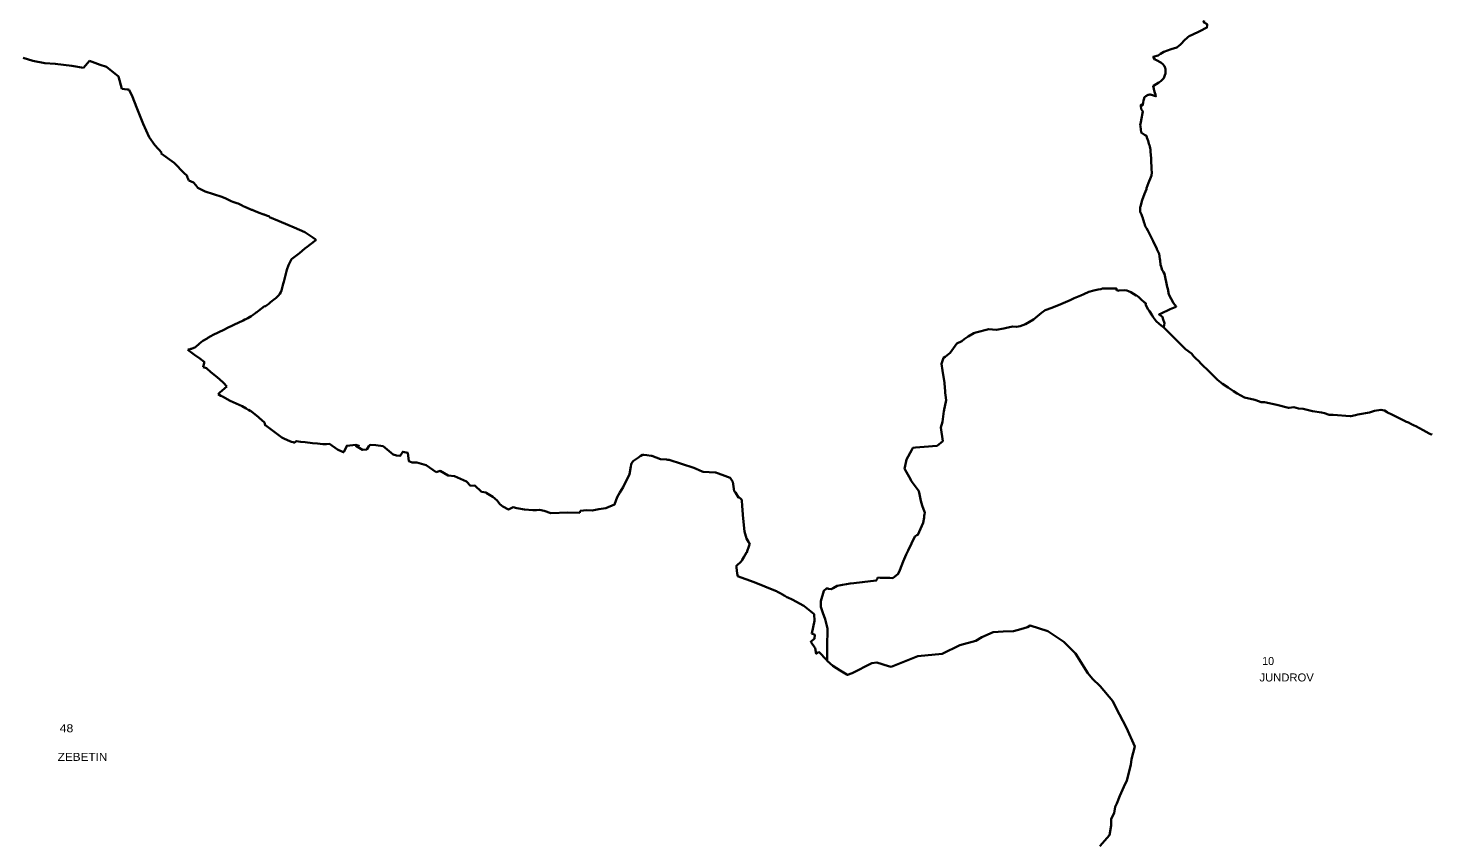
# Model space of a CAD drawing. Extents: x -610940 to -588976, y -1170376 to -1149800.
# Drawn here: x -606589 to -602206, y -1159085 to -1156549 of the extents above; entities that cross this region are included whole.
import ezdxf

# ---------------------------------------------------------------- set-up
doc = ezdxf.new("R2010")
doc.units = 0
doc.header["$LTSCALE"] = 10
doc.layers.add('54', color=7, linetype='Continuous', lineweight=35)
doc.layers.add('55', color=7, linetype='Continuous')
doc.layers.add('56', color=7, linetype='Continuous')

msp = doc.modelspace()

# ---------------------------------------------------------------- linework, layer by layer
at = {"layer": '54'}
for p, q in [((-606573.41, -1156650.86), (-606603.71, -1156641.95)), ((-606396.91, -1156651.1), (-606414.89, -1156673.42)), ((-603034.8, -1156681.8), (-603034.93, -1156679.37)), ((-603034.8, -1156681.8), (-603034.85, -1156683.02)), ((-606295.25, -1156738.29), (-606305.9, -1156699.88)), ((-603073.63, -1156729.42), (-603073.46, -1156730.15)), ((-603049.67, -1156714.63), (-603044.3, -1156709.82)), ((-606279.02, -1156740.64), (-606295.25, -1156738.29)), ((-606275.93, -1156741.06), (-606279.02, -1156740.64)), ((-606272.55, -1156741.59), (-606275.93, -1156741.06)), ((-606229.09, -1156847.84), (-606210.4, -1156889.81)), ((-603112.78, -1156864.59), (-603111.48, -1156875.56)), ((-603081.84, -1156935.53), (-603082.53, -1156928.02)), ((-606100.66, -1157001.65), (-606131.72, -1156970)), ((-603078.58, -1156989.29), (-603078.39, -1157000)), ((-606100.66, -1157001.65), (-606092.3, -1157009.86)), ((-606087.95, -1157021.2), (-606086.52, -1157024.94)), ((-603078.38, -1157000.43), (-603078.39, -1157000)), ((-605779.93, -1157304.38), (-605789.52, -1157341.15)), ((-603116.9, -1157391.36), (-603125, -1157384.6)), ((-605868.49, -1157431.81), (-605874.32, -1157436.06)), ((-605916.33, -1157462.45), (-605945.99, -1157476.16)), ((-605911.11, -1157459.6), (-605916.33, -1157462.45)), ((-603633.89, -1157501.46), (-603628.06, -1157500)), ((-603587.43, -1157489.81), (-603628.06, -1157500)), ((-606089.15, -1157553.88), (-606069.12, -1157569.32)), ((-606042.7, -1157526.16), (-606052.6, -1157534.3)), ((-606069.12, -1157569.32), (-606051.95, -1157581.07)), ((-605892.96, -1157745.6), (-605890.88, -1157746.83)), ((-605866.26, -1157766.65), (-605858.17, -1157773.65)), ((-603789.64, -1157857.17), (-603750, -1157853.93)), ((-603748.62, -1157853.82), (-603750, -1157853.93)), ((-605374.43, -1157906.2), (-605344.84, -1157914.66)), ((-605313.82, -1157936.32), (-605344.84, -1157914.66)), ((-604685.08, -1157892.41), (-604682.03, -1157890.35)), ((-604641.82, -1157884.71), (-604655.22, -1157883.26)), ((-604508.28, -1157922.95), (-604585.86, -1157897.85)), ((-604501.03, -1157926.09), (-604508.28, -1157922.95)), ((-604491.62, -1157930.16), (-604501.03, -1157926.09)), ((-604386.7, -1157966.54), (-604395.23, -1157953.95)), ((-605172.08, -1157997.16), (-605157.59, -1158000)), ((-604748.41, -1158014.07), (-604739.97, -1158000)), ((-604729.7, -1157982.86), (-604739.97, -1158000)), ((-604372.31, -1158010.18), (-604379.03, -1158000)), ((-603805.96, -1157996.34), (-603805.22, -1158000)), ((-603800.04, -1158025.65), (-603805.22, -1158000)), ((-604357.92, -1158042.78), (-604358.46, -1158022.44)), ((-605012.08, -1158054.79), (-605000, -1158054.25)), ((-604863.74, -1158056.76), (-604864.41, -1158063.43)), ((-604863.74, -1158056.76), (-604842.74, -1158054.43)), ((-604338, -1158171.27), (-604341.01, -1158179.49)), ((-603845.47, -1158193.51), (-603839.53, -1158180.77))]:
    msp.add_line(p, q, dxfattribs=at)
for points in [[(-602914.16, -1156525.16), (-602916.01, -1156530.62), (-602904.67, -1156536.87), (-602905.13, -1156540.83), (-602905.93, -1156547.63), (-602928.07, -1156558.76), (-602951.48, -1156569.64), (-602959.03, -1156572.94), (-602961.76, -1156574.66), (-602965.12, -1156577.39), (-602967.72, -1156579.56), (-602969.68, -1156581.02), (-602973.74, -1156584.7), (-602988.52, -1156600.46), (-603000.31, -1156609.81), (-603018.01, -1156614.46), (-603040.65, -1156622.62), (-603050.37, -1156629.17), (-603058.55, -1156635.02), (-603073.34, -1156638.27), (-603068.12, -1156647.34)], [(-606573.41, -1156650.86), (-606536.34, -1156658.8), (-606503.6, -1156660.38), (-606452.14, -1156666.63), (-606414.89, -1156673.42)], [(-606396.91, -1156651.1), (-606362.93, -1156663.95), (-606343.94, -1156670.15), (-606305.9, -1156699.88)], [(-603050.23, -1156656.21), (-603063.75, -1156649.51), (-603068.12, -1156647.34)], [(-603050.23, -1156656.21), (-603043.15, -1156662.04), (-603038.53, -1156667.58), (-603037.15, -1156671.3), (-603036.56, -1156672.87), (-603035.07, -1156676.88), (-603034.93, -1156679.37)], [(-603034.85, -1156683.02), (-603035.02, -1156687.18), (-603035.15, -1156690.41)], [(-603049.67, -1156714.63), (-603056.13, -1156718.62), (-603072.81, -1156728.91), (-603073.63, -1156729.42)], [(-603070.24, -1156744.38), (-603071.27, -1156739.71), (-603071.47, -1156738.78), (-603071.8, -1156737.29), (-603073.46, -1156730.15)], [(-603035.15, -1156690.41), (-603037.43, -1156696.51), (-603040.72, -1156705.29), (-603041.18, -1156706.54), (-603044.3, -1156709.82)], [(-606272.55, -1156741.59), (-606262.75, -1156763.75), (-606250.18, -1156795.61), (-606229.09, -1156847.84)], [(-603094.64, -1156760.15), (-603096.84, -1156761.67), (-603099.32, -1156764.09), (-603100.74, -1156766.05), (-603101.24, -1156765.7), (-603101.45, -1156766.01), (-603101.86, -1156766.62), (-603101.6, -1156766.91), (-603102.15, -1156769.25), (-603103.57, -1156775.21), (-603105.12, -1156781.69), (-603106.32, -1156786.76), (-603106.95, -1156789.38), (-603107.49, -1156791.64), (-603111.9, -1156788.31), (-603111.77, -1156791.52), (-603111.35, -1156802.03), (-603108.18, -1156805.99), (-603105.64, -1156809.15), (-603107, -1156815.15), (-603110.24, -1156831.56)], [(-603094.64, -1156760.15), (-603093.32, -1156759.25), (-603091.09, -1156758.37)], [(-603079.69, -1156757.46), (-603082.93, -1156756.36), (-603082.97, -1156756.03), (-603084.11, -1156756.11), (-603084.1, -1156756.42), (-603087.44, -1156757.02), (-603089.02, -1156757.54), (-603091.09, -1156758.37)], [(-603070.24, -1156744.38), (-603068.38, -1156750.95), (-603066.85, -1156756.39), (-603065.09, -1156762.62), (-603065.65, -1156761.87), (-603068.6, -1156760.91), (-603069.27, -1156760.69), (-603075.73, -1156758.89), (-603078.45, -1156757.7), (-603079.69, -1156757.46)], [(-603112.78, -1156864.59), (-603113.75, -1156856.37), (-603114.27, -1156851.99), (-603112.47, -1156842.88), (-603110.24, -1156831.56)], [(-606170.32, -1156938.72), (-606192.1, -1156915.02), (-606210.4, -1156889.81)], [(-603111.48, -1156875.56), (-603100.94, -1156881.89), (-603094.55, -1156885.54), (-603093.14, -1156890.78), (-603091.42, -1156896), (-603089.87, -1156900.74), (-603088.52, -1156904.85), (-603086.83, -1156909.97), (-603085.2, -1156914.95), (-603083.86, -1156919.01)], [(-606170.32, -1156938.72), (-606172.47, -1156940.95), (-606131.72, -1156970)], [(-603083.86, -1156919.01), (-603082.94, -1156923.63), (-603082.53, -1156928.02)], [(-603081.84, -1156935.53), (-603080.45, -1156954.96), (-603079.63, -1156967.88), (-603078.79, -1156981.16), (-603078.58, -1156989.29)], [(-606092.3, -1157009.86), (-606091.45, -1157012.07), (-606089.96, -1157015.98), (-606089.68, -1157016.71), (-606089.49, -1157017.2), (-606088.08, -1157020.87), (-606087.95, -1157021.2)], [(-606086.52, -1157024.94), (-606072.1, -1157031.2), (-606071.55, -1157031.44), (-606064.51, -1157040.08), (-606058.55, -1157047.39)], [(-603078.38, -1157000.43), (-603078.91, -1157009.19), (-603081.01, -1157014.45), (-603087.98, -1157032.76), (-603094.12, -1157048.89), (-603095, -1157051.86)], [(-606058.55, -1157047.39), (-606034.85, -1157059.67), (-605982.97, -1157075.63)], [(-605982.97, -1157075.63), (-605970.89, -1157081.48), (-605953.89, -1157089.71)], [(-603113.53, -1157105.82), (-603107.87, -1157086.39), (-603100.76, -1157066.93), (-603095, -1157051.86)], [(-605916.38, -1157105.06), (-605919.95, -1157103.34), (-605932.46, -1157097.31), (-605936.43, -1157095.9), (-605948.37, -1157091.67), (-605953.89, -1157089.71)], [(-605916.38, -1157105.06), (-605911.36, -1157107.47), (-605903.84, -1157110.7), (-605893.02, -1157115.34), (-605890.36, -1157116.44), (-605888.9, -1157117.05), (-605877.51, -1157121.69), (-605873.81, -1157123.2), (-605866.44, -1157125.93), (-605854.87, -1157130.22)], [(-603113.53, -1157105.82), (-603113.92, -1157107.15), (-603113.94, -1157123.29), (-603110.47, -1157131.42), (-603107.8, -1157137.7), (-603106.92, -1157139.74), (-603101.74, -1157156.71), (-603100.93, -1157159.34), (-603098.43, -1157167.56), (-603094.76, -1157174.16), (-603090.69, -1157181.5), (-603086.5, -1157189.06), (-603085.3, -1157191.22), (-603073.88, -1157214.92), (-603062.3, -1157238.93), (-603062.12, -1157239.32), (-603054.95, -1157254.44), (-603053.01, -1157269.63), (-603052.32, -1157275.01), (-603050.94, -1157288.34), (-603049.22, -1157293.47), (-603047.93, -1157297.29), (-603045.28, -1157305.17), (-603044.88, -1157306.37), (-603042.88, -1157309.52), (-603041.71, -1157311.48), (-603038.67, -1157316.16), (-603029.6, -1157357.49), (-603028.34, -1157363.01), (-603024.43, -1157381.29), (-603010.05, -1157408.23), (-603001.85, -1157418.6), (-603004.37, -1157419.73), (-603005.25, -1157420.13), (-603020.7, -1157427.07), (-603050.76, -1157441.27), (-603054.38, -1157442.98), (-603055.35, -1157443.44), (-603048.01, -1157448.87), (-603044.91, -1157451.16)], [(-605854.87, -1157130.22), (-605851.78, -1157131.37), (-605851.27, -1157131.56)], [(-605851.27, -1157131.56), (-605844.19, -1157133.88), (-605837.86, -1157136.32), (-605834.38, -1157137.76), (-605834.76, -1157139.34)], [(-605834.76, -1157139.34), (-605804.2, -1157152.12), (-605803.97, -1157152.21)], [(-605803.97, -1157152.21), (-605777.5, -1157163.14), (-605757.31, -1157171.38), (-605723.91, -1157186.34), (-605711.24, -1157194.51), (-605698.79, -1157203.3)], [(-605689.39, -1157210.6), (-605690.07, -1157211.14), (-605707.31, -1157224.77)], [(-605698.79, -1157203.3), (-605691.83, -1157208.7), (-605689.39, -1157210.6)], [(-605707.31, -1157224.77), (-605707.56, -1157224.97), (-605716.15, -1157231.73), (-605723.97, -1157237.89), (-605741.08, -1157251.49), (-605761.02, -1157267.13), (-605765.53, -1157270.66)], [(-605765.53, -1157270.66), (-605775.26, -1157289.92), (-605779.93, -1157304.38)], [(-605789.52, -1157341.15), (-605791.29, -1157347.58), (-605797.1, -1157368.66)], [(-605797.1, -1157368.66), (-605799.33, -1157374.23), (-605802.33, -1157379.45), (-605805.98, -1157384.26), (-605814.86, -1157392.88), (-605817.34, -1157395.11)], [(-603188.25, -1157368.25), (-603188.68, -1157361.87), (-603202.51, -1157362.08), (-603219.56, -1157362.48), (-603231.67, -1157362.59), (-603237.38, -1157364.13), (-603238.08, -1157364.13), (-603245.69, -1157365.32), (-603259.52, -1157368.99), (-603274.74, -1157373.03), (-603290.03, -1157379.62), (-603299.61, -1157383.73), (-603320.36, -1157392.59), (-603333.23, -1157398.28), (-603362.67, -1157411.26), (-603390.21, -1157422.46), (-603411.65, -1157430.17), (-603422.76, -1157438.03), (-603447.83, -1157458.88), (-603473.02, -1157474.08), (-603489.01, -1157480.15), (-603501, -1157482.3), (-603513.62, -1157481.52), (-603536.13, -1157485.98), (-603540.38, -1157486.82), (-603564.1, -1157491.61), (-603587.43, -1157489.81)], [(-603188.25, -1157368.25), (-603184.38, -1157367.99), (-603184.19, -1157369.38), (-603180.83, -1157368.82), (-603163.78, -1157367.31), (-603156.43, -1157368.15), (-603150.52, -1157370.19), (-603143.74, -1157373.56), (-603127.02, -1157384.2)], [(-603127.02, -1157384.2), (-603125.56, -1157385.13), (-603125, -1157384.6)], [(-603044.91, -1157451.16), (-603043.25, -1157455.92), (-603038.19, -1157470.39), (-603039.69, -1157476.65), (-603040.22, -1157480.27), (-603040.73, -1157484.29), (-603048.91, -1157477.92), (-603055.31, -1157472.67), (-603064.29, -1157464.68), (-603064.66, -1157464.25), (-603070.23, -1157456.23), (-603073.26, -1157451.87), (-603077.84, -1157444.84), (-603085.58, -1157433.04), (-603089.01, -1157427.7), (-603097.7, -1157411.86), (-603097.11, -1157411.21), (-603095.88, -1157409.79), (-603099.04, -1157407.5), (-603101, -1157406.09), (-603103.39, -1157404.37), (-603110.25, -1157398.16), (-603116.9, -1157391.36)], [(-605849.41, -1157417.46), (-605858.79, -1157424.51), (-605868.49, -1157431.81)], [(-605836.58, -1157410.15), (-605842.71, -1157414.79), (-605846.48, -1157417.65), (-605849.41, -1157417.46)], [(-605817.34, -1157395.11), (-605830.67, -1157405.53), (-605836.58, -1157410.15)], [(-605977.29, -1157491.2), (-605963.18, -1157484.1), (-605958.82, -1157482.09), (-605956.08, -1157480.83), (-605945.99, -1157476.16)], [(-605911.11, -1157459.6), (-605908.11, -1157457.97), (-605907.87, -1157457.83), (-605902.01, -1157454.52)], [(-605891.27, -1157448.43), (-605897.25, -1157451.82), (-605902.01, -1157454.52)], [(-605879.86, -1157440.1), (-605885.62, -1157444.3), (-605891.27, -1157448.43)], [(-605874.32, -1157436.06), (-605875.54, -1157436.95), (-605876.97, -1157437.99), (-605879.86, -1157440.1)], [(-606042.7, -1157526.16), (-606029.38, -1157518.25), (-606026.56, -1157516.58), (-606017.26, -1157511.06)], [(-605977.29, -1157491.2), (-606009.81, -1157507.23), (-606017.26, -1157511.06)], [(-603633.89, -1157501.46), (-603651.41, -1157512.27), (-603664.1, -1157521.1), (-603671.71, -1157526.39), (-603686.94, -1157534.03), (-603708.05, -1157563.34), (-603723.9, -1157575.31), (-603729.1, -1157579.2), (-603733.92, -1157594.91), (-603734.79, -1157597.76), (-603731.67, -1157618.59), (-603725.94, -1157656.78), (-603725.74, -1157659.52), (-603724.01, -1157682.76), (-603723.63, -1157687.73), (-603723.02, -1157695.94), (-603720.24, -1157710.98), (-603721.43, -1157716.46), (-603726.5, -1157739.78), (-603726.86, -1157742.6), (-603727.19, -1157745.22), (-603729.29, -1157761.65), (-603731.42, -1157778.47), (-603736.63, -1157796.58), (-603730.86, -1157838.87), (-603748.62, -1157853.82)], [(-603040.73, -1157484.29), (-603009.12, -1157515.75), (-602972.62, -1157551.75), (-602953.81, -1157565.5), (-602946.56, -1157574.75), (-602940.5, -1157581.25), (-602931.56, -1157589.5), (-602925.25, -1157596.75), (-602918.68, -1157603), (-602903.12, -1157617.75), (-602887.38, -1157632.62), (-602872.88, -1157647.62), (-602856.81, -1157659.75), (-602839.25, -1157671.5), (-602822.76, -1157682.79), (-602822.44, -1157682.5), (-602811.25, -1157690.25), (-602800, -1157697), (-602787.93, -1157703.25), (-602756.25, -1157709.99), (-602752.84, -1157711.21), (-602736.56, -1157717), (-602733.83, -1157717.72), (-602725.56, -1157717.62), (-602687.31, -1157725.37), (-602650.62, -1157735), (-602649.18, -1157734.99), (-602634.43, -1157733.25), (-602619.5, -1157737.25), (-602604.74, -1157737.99), (-602575.75, -1157746), (-602548.12, -1157749.37), (-602538.94, -1157752), (-602524.31, -1157757.25), (-602511.81, -1157757), (-602458.44, -1157760.87), (-602456.5, -1157760.87), (-602441.75, -1157758.12), (-602433.87, -1157756.37), (-602398, -1157749.74)], [(-606089.15, -1157553.88), (-606087.37, -1157553.32), (-606085.59, -1157552.76), (-606079.64, -1157550.88), (-606078.01, -1157550.36), (-606070.28, -1157547.91), (-606069.39, -1157547.63), (-606068.43, -1157547.33)], [(-606052.6, -1157534.3), (-606055.65, -1157536.81), (-606068.43, -1157547.33)], [(-606041.52, -1157607.82), (-606038.92, -1157594.16), (-606038.46, -1157591.78), (-606038.36, -1157591.24), (-606051.95, -1157581.07)], [(-606041.52, -1157607.82), (-606031.43, -1157611.52), (-606017.54, -1157623.33), (-606002.69, -1157634.76), (-605990.37, -1157645.05), (-605977.59, -1157657.1), (-605967.14, -1157668.26)], [(-605994.39, -1157692.55), (-605991.06, -1157689.44), (-605989.08, -1157687.68), (-605967.14, -1157668.26)], [(-605994.39, -1157692.55), (-605986.04, -1157697.13), (-605980.93, -1157699.93), (-605956.91, -1157713.1)], [(-605956.91, -1157713.1), (-605919.8, -1157729.83), (-605907.38, -1157737.13)], [(-605907.38, -1157737.13), (-605900.77, -1157741.02), (-605899.7, -1157741.64), (-605894.36, -1157744.78), (-605893.7, -1157745.18), (-605892.96, -1157745.6)], [(-602398, -1157749.74), (-602382.31, -1157744.74), (-602362.06, -1157741.5), (-602350.56, -1157743.87), (-602342.74, -1157748.76), (-602342.39, -1157748.98), (-602341.87, -1157749.21), (-602327.92, -1157756.07), (-602324.29, -1157757.86), (-602317.94, -1157761.01), (-602307.75, -1157766), (-602298.99, -1157770.35), (-602286.37, -1157776.62), (-602285.01, -1157777.25), (-602276.43, -1157781.24), (-602269.28, -1157784.8), (-602266.42, -1157786.22), (-602265.87, -1157786.5), (-602264.49, -1157787.2), (-602258.78, -1157790.13), (-602253.62, -1157792.83), (-602230.31, -1157805), (-602211.62, -1157815), (-602207, -1157817.24), (-602202.54, -1157818.76)], [(-605890.88, -1157746.83), (-605869.03, -1157764.42), (-605866.26, -1157766.65)], [(-605858.17, -1157773.65), (-605850.18, -1157780.56), (-605847.87, -1157789.29), (-605846.02, -1157790.57), (-605796.18, -1157827.53)], [(-605796.18, -1157827.53), (-605789.4, -1157830.91), (-605768.34, -1157839.9)], [(-605768.34, -1157839.9), (-605766.06, -1157841.24), (-605760.62, -1157842.29), (-605757.93, -1157843.37), (-605755.12, -1157843.79)], [(-605755.12, -1157843.79), (-605750.6, -1157839.05), (-605736.59, -1157841.45), (-605722.91, -1157842.28), (-605699.76, -1157845.2), (-605684.85, -1157846.01), (-605667.43, -1157848.73), (-605656.74, -1157848.32), (-605646.4, -1157847.97), (-605621.82, -1157864.7), (-605605.84, -1157872.38)], [(-605602.31, -1157874.05), (-605602.8, -1157873.62), (-605605.84, -1157872.38)], [(-605602.31, -1157874.05), (-605592.73, -1157853.26), (-605564.68, -1157850.76), (-605554.92, -1157853.36), (-605557.94, -1157853.36), (-605564.84, -1157853.36), (-605544.12, -1157866.36), (-605530.28, -1157865.12), (-605524.26, -1157854.96), (-605521.16, -1157851.68), (-605520.11, -1157850.83), (-605502.43, -1157851.9), (-605479.3, -1157854.94), (-605448.15, -1157881), (-605437.41, -1157884.09), (-605426.32, -1157885.4), (-605418.01, -1157872.39), (-605402.43, -1157875.88), (-605398.71, -1157901.79), (-605389.09, -1157905.87), (-605374.43, -1157906.2)], [(-603789.64, -1157857.17), (-603816.44, -1157859.33), (-603824.15, -1157859.95), (-603827.47, -1157865.92), (-603844.46, -1157896.5), (-603849.44, -1157921.73), (-603850.07, -1157924.92), (-603848.05, -1157928.61), (-603832.03, -1157957.74), (-603829.31, -1157962.69), (-603807.87, -1157992.29), (-603806.31, -1157994.44), (-603805.96, -1157996.34)], [(-604729.7, -1157982.86), (-604709.9, -1157941.92), (-604705.19, -1157918.08), (-604704.04, -1157912.26), (-604703.39, -1157908.95), (-604702.91, -1157908.29), (-604697.08, -1157900.33), (-604685.08, -1157892.41)], [(-604682.03, -1157890.35), (-604676.47, -1157886.55), (-604674.35, -1157885.1), (-604669.41, -1157881.72)], [(-604655.22, -1157883.26), (-604664.97, -1157882.2), (-604669.41, -1157881.72)], [(-604641.82, -1157884.71), (-604639.55, -1157885.51), (-604612.67, -1157894.94)], [(-604585.86, -1157897.85), (-604589.54, -1157897.45), (-604594.47, -1157896.92), (-604612.67, -1157894.94)], [(-605313.82, -1157936.32), (-605301.53, -1157932.19), (-605276.56, -1157946.85), (-605256.38, -1157948.35), (-605218.42, -1157964.84), (-605206.18, -1157978.64), (-605192.75, -1157977.83), (-605172.08, -1157997.16)], [(-604491.62, -1157930.16), (-604483.04, -1157933.87), (-604479.88, -1157935.24), (-604478.65, -1157935.31), (-604461.3, -1157936.23), (-604441.62, -1157937.28), (-604439.55, -1157937.39)], [(-604395.23, -1157953.95), (-604420.46, -1157944.52), (-604434.27, -1157939.36), (-604439.55, -1157937.39)], [(-605012.08, -1158054.79), (-605037.74, -1158053.13), (-605061.74, -1158048.47), (-605073.08, -1158045.47), (-605088.08, -1158052.14), (-605105.08, -1158043.48), (-605114.91, -1158035.57), (-605122.91, -1158024.23), (-605136.25, -1158013.24), (-605157.34, -1158000.05), (-605157.59, -1158000)], [(-604386.7, -1157966.54), (-604382.31, -1157995.03), (-604379.03, -1158000)], [(-604748.41, -1158014.07), (-604756.41, -1158037.41), (-604783.74, -1158048.41), (-604805.58, -1158051.17), (-604826.08, -1158055.75), (-604842.74, -1158054.43)], [(-604367.97, -1158013.91), (-604369.5, -1158015.32), (-604372.31, -1158010.18)], [(-604367.97, -1158013.91), (-604362.41, -1158018.66), (-604358.46, -1158022.44)], [(-604357.92, -1158042.78), (-604357.09, -1158052.88), (-604355.68, -1158070.04), (-604350.34, -1158121.7), (-604343.98, -1158143.38), (-604337.99, -1158153.9), (-604334.12, -1158160.7), (-604334.73, -1158162.37), (-604338, -1158171.27)], [(-603800.04, -1158025.65), (-603795.01, -1158040.2), (-603788.04, -1158060.38), (-603787.38, -1158062.3), (-603788.15, -1158067.78), (-603788.66, -1158071.46), (-603789.3, -1158075.99), (-603789.56, -1158077.89), (-603791.88, -1158094.42), (-603808.58, -1158131.34), (-603811.54, -1158132.99), (-603815.56, -1158135.23), (-603818.02, -1158136.59), (-603839.53, -1158180.77)], [(-604955.08, -1158064.45), (-604976.08, -1158057.12), (-604991.08, -1158054.12), (-605000, -1158054.25)], [(-604955.08, -1158064.45), (-604902.41, -1158062.1), (-604864.41, -1158063.43)], [(-604341.01, -1158179.49), (-604343.55, -1158186.42), (-604343.84, -1158187.2), (-604348.24, -1158194.53), (-604352.63, -1158201.85), (-604357.56, -1158210.07), (-604360.22, -1158214.5), (-604363.96, -1158217.99), (-604372.34, -1158225.8), (-604376.4, -1158229.58), (-604375.87, -1158233.42), (-604374.55, -1158242.98), (-604373.28, -1158252.18), (-604372.6, -1158257.12), (-604372.1, -1158260.74)], [(-603845.47, -1158193.51), (-603854.77, -1158214.59), (-603865.49, -1158241.83), (-603870.03, -1158253.36), (-603887.44, -1158266.85), (-603896.57, -1158266.55), (-603916.53, -1158265.88), (-603921.19, -1158265.73), (-603926.83, -1158265.54), (-603933.72, -1158265.31), (-603935.02, -1158267.7), (-603935.93, -1158269.38), (-603936.79, -1158270.97), (-603938.66, -1158274.42), (-603982.71, -1158279.98), (-604008.94, -1158282.59), (-604019.9, -1158283.68), (-604031.54, -1158285.75), (-604043.88, -1158287.95), (-604049.59, -1158288.96), (-604060.85, -1158290.97), (-604073.81, -1158298), (-604079.66, -1158301.17), (-604087.79, -1158300.07), (-604090.24, -1158299.73), (-604094.62, -1158299.14), (-604103.03, -1158306.79), (-604111.73, -1158338.56), (-604112.24, -1158352.17), (-604112.4, -1158356.38), (-604105.63, -1158375.03), (-604098.23, -1158395.42), (-604091.38, -1158424.68), (-604091.7, -1158483.13), (-604091.72, -1158486.93), (-604091.78, -1158498.6), (-604091.87, -1158515.6), (-604091.94, -1158525.2)], [(-604250.86, -1158307.49), (-604253.06, -1158306.26), (-604320.68, -1158279.88), (-604372.1, -1158260.74)], [(-604250.86, -1158307.49), (-604247.05, -1158309.63), (-604237.03, -1158315.26), (-604233.36, -1158317.33), (-604224.28, -1158322.44), (-604217.69, -1158326.14)], [(-604165.42, -1158353.94), (-604201.28, -1158333.38), (-604215.56, -1158327.34), (-604217.69, -1158326.14)], [(-604165.42, -1158353.94), (-604144.52, -1158370.65), (-604133.3, -1158379.62)], [(-604118.5, -1158497.4), (-604126.3, -1158503.2), (-604129.34, -1158486.26), (-604143.44, -1158465.64), (-604131.54, -1158455.64), (-604130.32, -1158444.26), (-604140.38, -1158440.42), (-604131.22, -1158400.06), (-604133.3, -1158379.62)], [(-603240.3, -1159104.18), (-603210.47, -1159069.53), (-603205.27, -1159039.17), (-603204.5, -1159019.08), (-603195.81, -1159001.52), (-603192.42, -1158981.65), (-603186.91, -1158971.04), (-603177.53, -1158946.72), (-603164.99, -1158918.76), (-603156.42, -1158899.39), (-603143.72, -1158850.44), (-603141.93, -1158832.83), (-603135.75, -1158812.4), (-603131.28, -1158792.78), (-603156.67, -1158734.53), (-603190.83, -1158670.95), (-603200.06, -1158651.12), (-603239.63, -1158604.1), (-603263.16, -1158581.42), (-603277.55, -1158563.85), (-603316.17, -1158501.97), (-603352.84, -1158465.74), (-603402.48, -1158432.9), (-603458.02, -1158415.27), (-603465.89, -1158420.08), (-603487.62, -1158426.46), (-603510.14, -1158432.66), (-603542.69, -1158433.27), (-603573.51, -1158436.16), (-603608.5, -1158451.23), (-603627.46, -1158462.57), (-603678.23, -1158476.84), (-603732.7, -1158503.7), (-603809.01, -1158511.04), (-603891.9, -1158544.56)], [(-604091.94, -1158525.2), (-604093.62, -1158523.44), (-604118.5, -1158497.4)], [(-603891.9, -1158544.56), (-603900.27, -1158542.04), (-603936.54, -1158530.09), (-603952.3, -1158533.08), (-604013.78, -1158564.1), (-604028.4, -1158569.5), (-604030.71, -1158568.15), (-604051.72, -1158555.72), (-604074.55, -1158541.09), (-604091.94, -1158525.2)]]:
    msp.add_lwpolyline(points, dxfattribs=at)

# ---------------------------------------------------------------- texts
at = {"layer": '55'}
for s, width, p in [('JUNDROV ', 1.05, (-602741.69, -1158589.71)), ('ZEBETIN ', 1.1, (-606496.02, -1158837.8))]:
    msp.add_text(s, height=25, dxfattribs=dict(at, width=width)).set_placement(p)
at = {"layer": '56'}
msp.add_text('10 ', height=25, dxfattribs=at).set_placement((-602733.28, -1158538.29))
at = {"layer": '56', "width": 1.15}
msp.add_text('48 ', height=25, dxfattribs=at).set_placement((-606489.94, -1158748.39))

doc.saveas('drawing.dxf')
